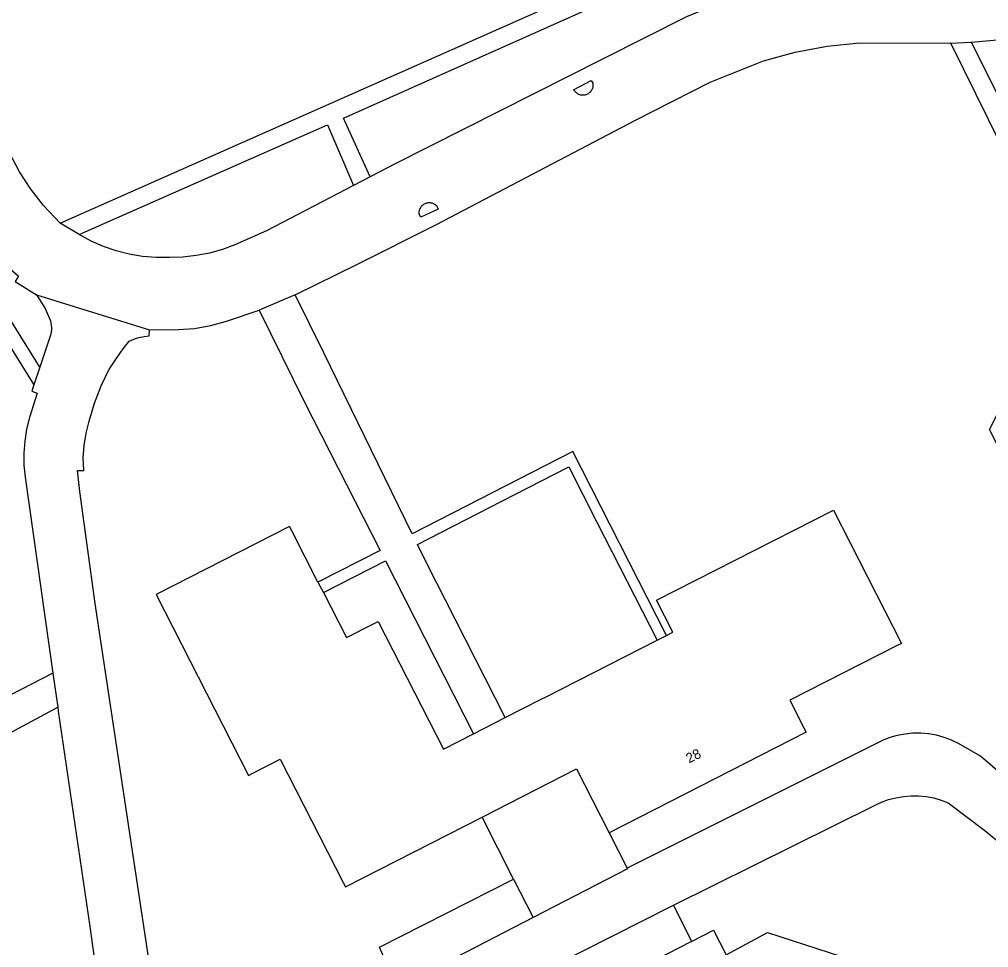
# Model space of a CAD drawing. Extents: x 158132 to 159658, y 385257 to 387209.
# Drawn here: x 158829.4 to 158926.9, y 386462.6 to 386556 of the extents above; entities that cross this region are included whole.
import ezdxf

# ---------------------------------------------------------------- set-up
doc = ezdxf.new("R2010")
doc.units = 0
for name, color, linetype in [('IMGEO_Pand', 7, 'Continuous'), ('IMGEO_Pand_nummerreeks', 7, 'Continuous'), ('IMGEO_Parkeervlak_open', 7, 'Continuous'), ('IMGEO_Rijbaan_lokaal_gesloten', 7, 'Continuous'), ('IMGEO_Voetpad_open', 7, 'Continuous')]:
    doc.layers.add(name, color=color, linetype=linetype)

msp = doc.modelspace()

# ---------------------------------------------------------------- linework, layer by layer
at = {"layer": 'IMGEO_Pand'}
for points in [[(158894.526, 386494.007), (158895.136, 386494.318), (158893.491, 386497.55), (158911.316, 386506.621), (158918.144, 386493.203), (158917.699, 386492.976), (158906.903, 386487.483), (158908.32, 386484.705), (158908.548, 386484.26), (158888.74, 386474.153)], [(158859.457, 386499.365), (158856.813, 386504.526), (158856.585, 386504.971), (158843.179, 386498.127), (158852.464, 386479.921), (158852.91, 386480.146), (158855.664, 386481.539), (158861.99, 386469.162), (158862.218, 386468.717), (158875.973, 386475.727)], [(158859.457, 386499.365), (158859.998, 386498.308)], [(158859.998, 386498.308), (158862.317, 386493.782), (158865.058, 386495.164), (158865.505, 386495.389), (158872.068, 386482.557), (158875.109, 386484.108)], [(158878.302, 386485.736), (158881.911, 386487.576), (158882.356, 386487.803), (158893.561, 386493.515)], [(158893.561, 386493.515), (158894.526, 386494.007)], [(158875.109, 386484.108), (158878.302, 386485.736)], [(158875.973, 386475.727), (158885.475, 386480.569), (158888.74, 386474.153)], [(158897.035, 386463.208), (158899.246, 386464.336), (158900.513, 386461.854), (158904.683, 386464.1), (158914.602, 386460.885)], [(158897.035, 386463.208), (158893.295, 386461.299), (158893.993, 386459.999), (158886.117, 386455.979), (158885.64, 386454.509), (158883.535, 386453.434), (158882.075, 386453.908), (158874.218, 386449.898), (158873.447, 386451.409), (158872.415, 386450.882)]]:
    msp.add_lwpolyline(points, dxfattribs=at)
at = {"layer": 'IMGEO_Parkeervlak_open'}
msp.add_lwpolyline([(158867.423, 386458.544), (158865.631, 386462.643), (158879.137, 386469.497)], dxfattribs=at)
at = {"layer": 'IMGEO_Rijbaan_lokaal_gesloten'}
for points in [[(158833.528, 386535.481), (158831.85, 386537.267), (158830.562, 386538.899), (158829.431, 386540.642), (158828.465, 386542.482), (158827.673, 386544.404), (158823.219, 386558.591), (158818.274, 386573.982)], [(158916.604, 386560.747), (158915.942, 386560.751), (158911.811, 386560.551), (158909.029, 386560.169), (158905.296, 386559.356), (158900.722, 386557.985), (158896.528, 386556.235), (158888.134, 386552.008), (158867.232, 386541.45), (158864.7, 386540.134)], [(158857.168, 386528.288), (158863.436, 386531.345), (158871.296, 386535.33), (158891.4, 386545.834), (158898.915, 386549.666), (158904.28, 386551.816), (158907.444, 386552.684), (158910.668, 386553.289), (158913.931, 386553.627), (158923.02, 386553.593), (158923.1, 386553.597)], [(158923.1, 386553.597), (158925.12, 386553.695), (158925.181, 386553.7)], [(158925.181, 386553.7), (158927.784, 386553.931)], [(158887.033, 386548.974), (158886.996, 386548.894), (158886.951, 386548.818), (158886.9, 386548.746), (158886.843, 386548.678), (158886.78, 386548.616), (158886.712, 386548.559), (158886.64, 386548.509), (158886.563, 386548.465), (158886.483, 386548.428), (158886.4, 386548.398), (158886.314, 386548.376), (158886.227, 386548.36), (158886.139, 386548.353), (158886.051, 386548.353), (158885.963, 386548.361), (158885.876, 386548.376), (158885.791, 386548.399), (158885.708, 386548.429), (158885.628, 386548.467), (158885.551, 386548.511), (158885.479, 386548.562), (158885.411, 386548.618), (158885.349, 386548.681), (158885.16, 386548.902), (158886.942, 386549.837), (158887.091, 386549.58), (158887.105, 386549.493), (158887.112, 386549.405), (158887.112, 386549.316), (158887.103, 386549.229), (158887.088, 386549.142), (158887.064, 386549.057), (158887.033, 386548.974)], [(158864.7, 386540.134), (158863.027, 386539.265)], [(158863.027, 386539.265), (158854.273, 386534.715), (158851.105, 386533.305), (158849.838, 386532.84), (158848.538, 386532.478), (158847.213, 386532.22), (158845.872, 386532.069), (158844.524, 386532.025), (158843.166, 386532.021), (158841.812, 386532.131), (158840.472, 386532.354), (158839.156, 386532.689), (158837.873, 386533.134), (158836.632, 386533.685), (158835.441, 386534.338)], [(158871.429, 386537.182), (158871.537, 386536.904), (158869.795, 386536.087), (158869.664, 386536.332), (158869.65, 386536.418), (158869.643, 386536.504), (158869.643, 386536.591), (158869.651, 386536.677), (158869.666, 386536.762), (158869.688, 386536.846), (158869.718, 386536.928), (158869.754, 386537.006), (158869.797, 386537.082), (158869.846, 386537.153), (158869.902, 386537.22), (158869.963, 386537.281), (158870.029, 386537.338), (158870.099, 386537.388), (158870.174, 386537.432), (158870.252, 386537.47), (158870.333, 386537.501), (158870.416, 386537.524), (158870.501, 386537.541), (158870.588, 386537.55), (158870.674, 386537.551), (158870.761, 386537.545), (158870.846, 386537.532), (158870.931, 386537.511), (158871.013, 386537.484), (158871.092, 386537.449), (158871.168, 386537.407), (158871.241, 386537.36), (158871.308, 386537.306), (158871.372, 386537.246), (158871.429, 386537.182)], [(158835.441, 386534.338), (158833.528, 386535.481)], [(158828.439, 386530.95), (158828.485, 386530.899), (158829.343, 386530.155), (158828.995, 386529.605), (158831.151, 386528.263)], [(158831.151, 386528.263), (158842.504, 386524.752)], [(158831.151, 386528.263), (158832.026, 386526.892), (158832.54, 386525.667), (158832.596, 386525.447), (158832.633, 386525.223), (158832.65, 386524.996), (158832.647, 386524.769), (158832.623, 386524.543), (158832.58, 386524.32), (158832.518, 386524.102), (158831.481, 386520.991)], [(158857.168, 386528.288), (158853.538, 386526.713)], [(158842.504, 386524.752), (158845.38, 386524.772), (158847.034, 386524.895), (158848.667, 386525.184), (158850.263, 386525.635), (158853.538, 386526.713)], [(158843.41, 386455.607), (158842.779, 386459.203), (158837.046, 386497.213), (158835.493, 386508.496), (158835.271, 386510.606), (158835.892, 386510.604), (158835.855, 386511.857), (158835.934, 386513.108), (158836.131, 386514.347), (158836.444, 386515.561), (158836.968, 386517.36), (158837.638, 386519.109), (158838.451, 386520.798), (158838.481, 386520.841), (158839.104, 386521.748), (158839.772, 386522.688), (158840.455, 386523.617), (158840.945, 386523.82), (158841.451, 386523.979), (158841.968, 386524.093), (158842.494, 386524.162), (158842.504, 386524.752)], [(158831.481, 386520.991), (158830.888, 386519.209)], [(158830.888, 386519.209), (158830.682, 386518.593), (158831.22, 386518.39), (158830.427, 386515.934), (158830.144, 386514.755), (158829.959, 386513.557), (158829.872, 386512.348), (158829.884, 386511.136), (158829.995, 386509.929), (158832.794, 386490.221)], [(158832.794, 386490.221), (158833.28, 386486.797)], [(158833.28, 386486.797), (158833.337, 386486.394), (158836.519, 386464.72), (158837.646, 386456.472), (158838.599, 386450.545), (158839.041, 386435.132), (158838.72, 386431.532), (158839.475, 386431.51), (158839.414, 386431.051)], [(158931.818, 386476.281), (158932.114, 386476.655), (158926.097, 386481.871), (158923.887, 386483.127), (158923.172, 386483.471), (158922.428, 386483.749), (158921.663, 386483.959), (158920.881, 386484.098), (158920.091, 386484.166), (158919.297, 386484.162), (158918.507, 386484.087), (158917.727, 386483.94), (158916.964, 386483.723), (158916.223, 386483.438), (158890.559, 386470.579)], [(158895.223, 386466.883), (158915.436, 386476.892), (158916.129, 386477.218), (158916.848, 386477.482), (158917.588, 386477.68), (158918.343, 386477.811), (158919.106, 386477.874), (158919.873, 386477.869), (158920.636, 386477.796), (158921.39, 386477.654), (158922.128, 386477.446), (158922.844, 386477.173), (158926.524, 386474.377), (158928.799, 386472.509)], [(158890.559, 386470.579), (158890.595, 386470.508), (158881.104, 386465.624)], [(158870.678, 386454.451), (158895.223, 386466.883)], [(158881.104, 386465.624), (158867.423, 386458.544)]]:
    msp.add_lwpolyline(points, dxfattribs=at)
at = {"layer": 'IMGEO_Voetpad_open'}
for points in [[(158833.528, 386535.481), (158904.424, 386566.953), (158911.325, 386567.095), (158894.347, 386587.559)], [(158864.7, 386540.134), (158862.009, 386546.043), (158905.257, 386565.368), (158912.811, 386565.304), (158916.604, 386560.747)], [(158946.708, 386475.345), (158927.013, 386514.714), (158931.107, 386522.837), (158936.964, 386525.527), (158923.1, 386553.597)], [(158943.976, 386529.104), (158938.844, 386526.305), (158925.181, 386553.7)], [(158815.114, 386550.18), (158820.639, 386532.177), (158824.465, 386529.474), (158830.888, 386519.209)], [(158835.441, 386534.338), (158860.413, 386545.384), (158863.027, 386539.265)], [(158831.481, 386520.991), (158825.963, 386529.85), (158828.439, 386530.95)], [(158894.526, 386494.007), (158885.099, 386512.501), (158868.942, 386504.224), (158860.038, 386522.423), (158857.168, 386528.288)], [(158853.538, 386526.713), (158858.103, 386517.457), (158865.698, 386502.562), (158859.457, 386499.365)], [(158878.302, 386485.736), (158872.242, 386497.619), (158870.538, 386500.962), (158869.464, 386503.157), (158877.936, 386507.498), (158884.679, 386510.952), (158887.508, 386505.403), (158893.561, 386493.515)], [(158859.998, 386498.308), (158866.237, 386501.505), (158875.109, 386484.108)], [(158832.794, 386490.221), (158825.288, 386486.356), (158817.956, 386482.581), (158813.281, 386480.174)], [(158814.867, 386477.093), (158824.089, 386481.841), (158833.28, 386486.797)], [(158879.137, 386469.497), (158875.973, 386475.727)], [(158888.74, 386474.153), (158890.559, 386470.579)], [(158879.137, 386469.497), (158881.104, 386465.624)], [(158895.223, 386466.883), (158897.035, 386463.208)]]:
    msp.add_lwpolyline(points, dxfattribs=at)

# ---------------------------------------------------------------- texts
at = {"layer": 'IMGEO_Pand_nummerreeks'}
msp.add_text('28', height=1, rotation=26.90037, dxfattribs=at).set_placement((158896.777, 386481.111))

doc.saveas('drawing.dxf')
